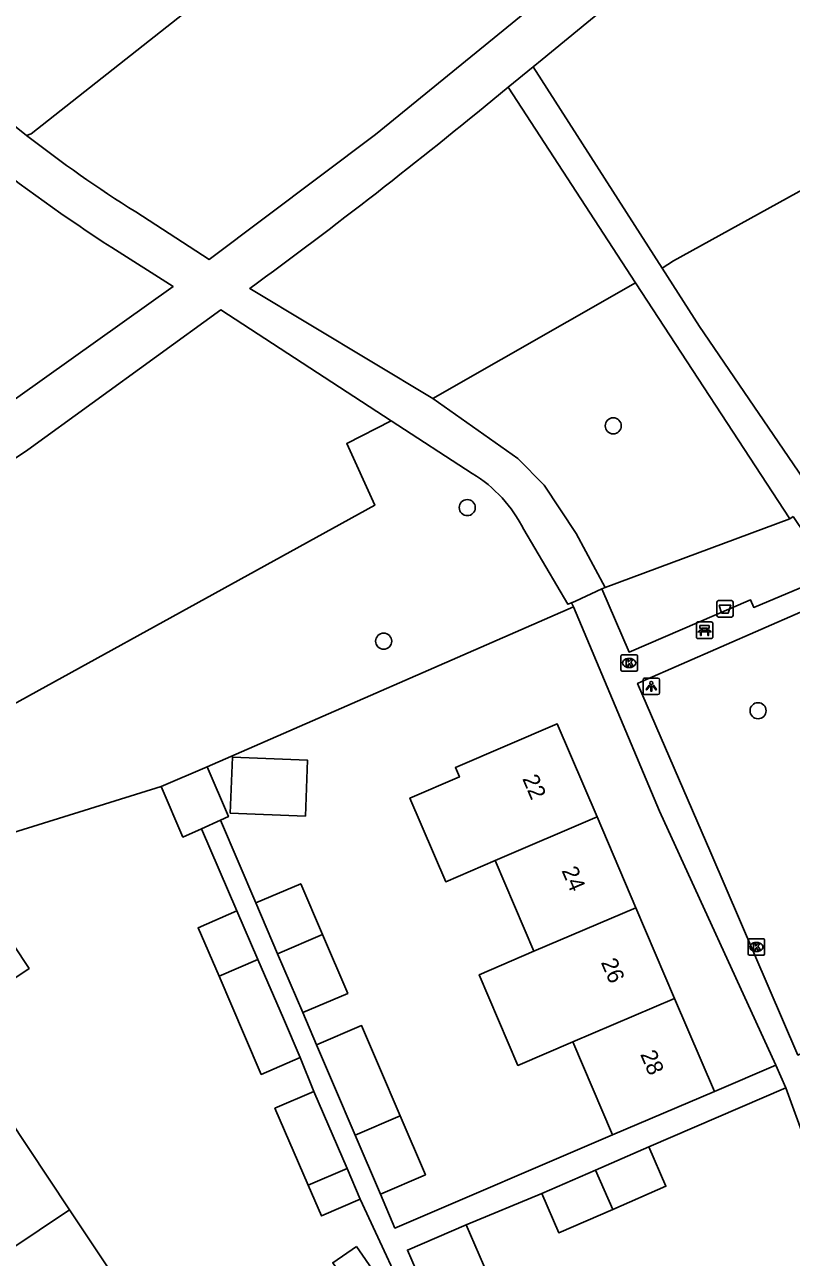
# Model space of a CAD drawing. Extents: x 159353 to 160616, y 385893 to 387321.
# Drawn here: x 159577.9 to 159624.6, y 386440.7 to 386515.7 of the extents above; entities that cross this region are included whole.
import ezdxf

# ---------------------------------------------------------------- set-up
doc = ezdxf.new("R2010")
doc.units = 0
for name, color, linetype in [('IMGEO_Afvalbak', 7, 'Continuous'), ('IMGEO_Bank', 7, 'Continuous'), ('IMGEO_Boom', 7, 'Continuous'), ('IMGEO_Groenvoorziening', 7, 'Continuous'), ('IMGEO_Kolk', 7, 'Continuous'), ('IMGEO_Lichtpunt', 7, 'Continuous'), ('IMGEO_Loofbos', 7, 'Continuous'), ('IMGEO_Pand', 7, 'Continuous'), ('IMGEO_Pand_nummerreeks', 7, 'Continuous'), ('IMGEO_Voetpad_halfverhard', 7, 'Continuous'), ('IMGEO_Voetpad_open', 7, 'Continuous')]:
    doc.layers.add(name, color=color, linetype=linetype)

msp = doc.modelspace()

# ---------------------------------------------------------------- linework, layer by layer
at = {"layer": 'IMGEO_Afvalbak'}
for p, q in [((159620.026, 386479.748), (159620.026, 386480.548)), ((159620.026, 386480.548), (159620.026, 386479.748)), ((159620.126, 386480.648), (159620.916, 386480.648)), ((159620.916, 386480.648), (159620.126, 386480.648)), ((159621.016, 386480.548), (159621.016, 386479.748)), ((159621.016, 386479.748), (159621.016, 386480.548)), ((159620.916, 386479.648), (159620.126, 386479.648)), ((159620.126, 386479.648), (159620.916, 386479.648))]:
    msp.add_line(p, q, dxfattribs=at)
msp.add_lwpolyline([(159620.169, 386480.362), (159620.873, 386480.362), (159620.724, 386479.892), (159620.318, 386479.892), (159620.169, 386480.362)], dxfattribs=at)
for centre, start, end in [((159620.126, 386480.548), 90, 180), ((159620.126, 386480.548), 90, 180), ((159620.916, 386480.548), 0, 90), ((159620.916, 386480.548), 360, 90), ((159620.126, 386479.748), 180, 270), ((159620.126, 386479.748), 180, 270), ((159620.916, 386479.748), 270, 0), ((159620.916, 386479.748), 270, 0)]:
    msp.add_arc(centre, 0.1, start, end, dxfattribs=at)
at = {"layer": 'IMGEO_Bank'}
for p, q in [((159618.777, 386478.421), (159618.777, 386479.262)), ((159618.777, 386479.262), (159618.777, 386478.421)), ((159618.852, 386479.346), (159619.693, 386479.346)), ((159619.693, 386479.346), (159618.852, 386479.346)), ((159619.086, 386478.852), (159619.086, 386478.958)), ((159619.13, 386478.958), (159619.13, 386478.852)), ((159619.418, 386478.964), (159619.136, 386478.964)), ((159619.136, 386478.846), (159619.418, 386478.846)), ((159619.424, 386478.852), (159619.424, 386478.958)), ((159619.468, 386478.958), (159619.468, 386478.852)), ((159619.777, 386479.271), (159619.777, 386478.43)), ((159619.777, 386478.43), (159619.777, 386479.271)), ((159619.702, 386478.346), (159618.861, 386478.346)), ((159618.861, 386478.346), (159619.702, 386478.346)), ((159619.474, 386478.744), (159619.081, 386478.744))]:
    msp.add_line(p, q, dxfattribs=at)
for points in [[(159619.024, 386478.744), (159618.882, 386478.744), (159618.994, 386478.846), (159619.08, 386478.846)], [(159619.08, 386478.964), (159618.994, 386478.964), (159618.994, 386479.125), (159619.557, 386479.125), (159619.557, 386478.964), (159619.474, 386478.964)], [(159619.474, 386478.846), (159619.557, 386478.846), (159619.669, 386478.744), (159619.53, 386478.744)], [(159619.074, 386478.737), (159619.074, 386478.53), (159619.031, 386478.53), (159619.031, 386478.737)], [(159619.524, 386478.737), (159619.524, 386478.53), (159619.48, 386478.53), (159619.48, 386478.737)]]:
    msp.add_lwpolyline(points, dxfattribs=at)
for centre, radius, start, end in [((159618.855, 386479.268), 0.0779, 92.4484, 184.28452), ((159618.855, 386479.268), 0.0779, 92.4484, 184.28452), ((159619.079, 386478.957), 0.00671, 2.89567, 87.10433), ((159619.079, 386478.853), 0.00671, 272.89567, 357.10433), ((159619.136, 386478.957), 0.00671, 92.89567, 177.10433), ((159619.136, 386478.853), 0.00671, 182.89567, 267.10433), ((159619.418, 386478.957), 0.00671, 2.89567, 87.10433), ((159619.418, 386478.853), 0.00671, 272.89567, 357.10433), ((159619.475, 386478.957), 0.00671, 92.89567, 177.10433), ((159619.475, 386478.853), 0.00671, 182.89567, 267.10433), ((159619.699, 386479.268), 0.0779, 2.4484, 94.28452), ((159619.699, 386479.268), 0.0779, 2.4484, 94.28452), ((159618.855, 386478.424), 0.0779, 182.4484, 274.28452), ((159618.855, 386478.424), 0.0779, 182.4484, 274.28452), ((159619.024, 386478.737), 0.00671, 2.89567, 87.10433), ((159619.081, 386478.737), 0.00671, 92.89567, 177.10433), ((159619.473, 386478.737), 0.00671, 2.89567, 87.10433), ((159619.53, 386478.737), 0.00671, 92.89567, 177.10433), ((159619.699, 386478.424), 0.0779, 272.4484, 4.28452), ((159619.699, 386478.424), 0.0779, 272.4484, 4.28452)]:
    msp.add_arc(centre, radius, start, end, dxfattribs=at)
at = {"layer": 'IMGEO_Boom'}
for centre in [(159613.716, 386491.293), (159604.823, 386486.312), (159599.729, 386478.177), (159622.534, 386473.944)]:
    msp.add_circle(centre, 0.489, dxfattribs=at)
at = {"layer": 'IMGEO_Groenvoorziening'}
for points in [[(159667.147, 386524.973), (159656.794, 386519.346), (159660.037, 386510.81), (159635.305, 386500), (159633.396, 386499.166), (159632.966, 386500), (159628.972, 386507.732), (159617.387, 386501.341), (159616.698, 386500.899)], [(159615.073, 386500), (159602.715, 386492.962)], [(159600.187, 386491.603), (159597.482, 386490.226), (159599.199, 386486.465), (159568.818, 386469.742), (159563.351, 386479.984)], [(159624.463, 386485.638), (159613.22, 386481.445)], [(159611.284, 386480.27), (159588.978, 386470.532)], [(159569.941, 386464.28), (159586.179, 386469.337)]]:
    msp.add_lwpolyline(points, dxfattribs=at)
at = {"layer": 'IMGEO_Kolk'}
for p, q in [((159614.26, 386477.351), (159615.112, 386477.351)), ((159614.185, 386476.425), (159614.185, 386477.277)), ((159614.696, 386476.571), (159614.671, 386476.571)), ((159614.673, 386477.131), (159614.698, 386477.131)), ((159615.186, 386477.277), (159615.186, 386476.425)), ((159615.112, 386476.351), (159614.26, 386476.351)), ((159622.009, 386460.055), (159622.861, 386460.055)), ((159621.934, 386459.129), (159621.934, 386459.981)), ((159622.422, 386459.835), (159622.447, 386459.835)), ((159622.935, 386459.981), (159622.935, 386459.129)), ((159622.861, 386459.055), (159622.009, 386459.055)), ((159622.445, 386459.275), (159622.42, 386459.275))]:
    msp.add_line(p, q, dxfattribs=at)
for points in [[(159614.26, 386477.351), (159615.112, 386477.351)], [(159614.185, 386476.425), (159614.185, 386477.277)], [(159614.506, 386477.051), (159614.629, 386477.051), (159614.629, 386476.9), (159614.759, 386477.051), (159614.923, 386477.051), (159614.777, 386476.9), (159614.93, 386476.651), (159614.778, 386476.651), (159614.693, 386476.815), (159614.629, 386476.748), (159614.629, 386476.651), (159614.506, 386476.651), (159614.506, 386477.051)], [(159615.186, 386477.277), (159615.186, 386476.425)], [(159615.112, 386476.351), (159614.26, 386476.351)], [(159622.009, 386460.055), (159622.861, 386460.055)], [(159621.934, 386459.129), (159621.934, 386459.981)], [(159622.255, 386459.755), (159622.378, 386459.755), (159622.378, 386459.604), (159622.508, 386459.755), (159622.672, 386459.755), (159622.526, 386459.604), (159622.679, 386459.355), (159622.527, 386459.355), (159622.442, 386459.519), (159622.378, 386459.452), (159622.378, 386459.355), (159622.255, 386459.355), (159622.255, 386459.755)], [(159622.935, 386459.981), (159622.935, 386459.129)], [(159622.861, 386459.055), (159622.009, 386459.055)]]:
    msp.add_lwpolyline(points, dxfattribs=at)
for centre, start, end in [((159614.262, 386477.275), 91.55205, 178.44795), ((159614.262, 386477.275), 91.55205, 178.44795), ((159615.11, 386477.275), 1.55205, 88.44795), ((159615.11, 386477.275), 1.55205, 88.44795), ((159614.262, 386476.427), 181.55205, 268.44795), ((159614.262, 386476.427), 181.55205, 268.44795), ((159615.11, 386476.427), 271.55205, 358.44795), ((159615.11, 386476.427), 271.55205, 358.44795), ((159622.011, 386459.979), 91.55205, 178.44795), ((159622.011, 386459.979), 91.55205, 178.44795), ((159622.859, 386459.979), 1.55205, 88.44795), ((159622.859, 386459.979), 1.55205, 88.44795), ((159622.011, 386459.131), 181.55205, 268.44795), ((159622.011, 386459.131), 181.55205, 268.44795), ((159622.859, 386459.131), 271.55205, 358.44795), ((159622.859, 386459.131), 271.55205, 358.44795)]:
    msp.add_arc(centre, 0.0765, start, end, dxfattribs=at)
for centre, major_axis, ratio, start_param, end_param in [((159614.672, 386476.851), (-0.387, 0.002), 0.722429, 4.712389, 7.853982), ((159614.697, 386476.851), (-0.39, 0.002), 0.717154, 1.570796, 4.712389), ((159622.421, 386459.555), (-0.387, 0.002), 0.722429, 4.712389, 7.853982), ((159622.446, 386459.555), (-0.39, 0.002), 0.717154, 1.570796, 4.712389)]:
    msp.add_ellipse(centre, major_axis=major_axis, ratio=ratio, start_param=start_param, end_param=end_param, dxfattribs=at)
at = {"layer": 'IMGEO_Lichtpunt'}
for p, q in [((159615.534, 386475.832), (159615.534, 386475.025)), ((159615.534, 386475.832), (159615.534, 386475.025)), ((159616.436, 386475.927), (159615.628, 386475.927)), ((159616.436, 386475.927), (159615.628, 386475.927)), ((159616.53, 386475.025), (159616.53, 386475.832)), ((159616.53, 386475.025), (159616.53, 386475.832)), ((159615.628, 386474.931), (159616.436, 386474.931)), ((159615.628, 386474.931), (159616.436, 386474.931))]:
    msp.add_line(p, q, dxfattribs=at)
for points in [[(159615.908, 386475.496), (159615.947, 386475.468), (159615.759, 386475.206), (159615.721, 386475.233), (159615.908, 386475.496)], [(159616.01, 386475.448), (159616.057, 386475.448), (159616.057, 386475.126), (159616.01, 386475.126), (159616.01, 386475.448)], [(159616.12, 386475.468), (159616.158, 386475.495), (159616.345, 386475.233), (159616.306, 386475.205), (159616.12, 386475.468)]]:
    msp.add_lwpolyline(points, dxfattribs=at)
msp.add_circle((159616.033, 386475.63), 0.0994, dxfattribs=at)
for centre, start, end in [((159615.628, 386475.832), 90, 180), ((159615.628, 386475.832), 90, 180), ((159616.436, 386475.832), 0, 90), ((159616.436, 386475.832), 0, 90), ((159615.628, 386475.025), 180, 270), ((159615.628, 386475.025), 180, 270), ((159616.436, 386475.025), 270, 0), ((159616.436, 386475.025), 270, 360)]:
    msp.add_arc(centre, 0.0946, start, end, dxfattribs=at)
at = {"layer": 'IMGEO_Loofbos'}
msp.add_lwpolyline([(159577.978, 386508.983), (159578.254, 386509.068), (159625.523, 386546.373), (159634.736, 386539.418)], dxfattribs=at)
at = {"layer": 'IMGEO_Pand'}
for points in [[(159606.521, 386464.816), (159603.51, 386463.528), (159601.33, 386468.622), (159604.341, 386469.91), (159604.098, 386470.479), (159610.303, 386473.134), (159612.726, 386467.471)], [(159594.961, 386467.526), (159590.383, 386467.711), (159590.521, 386471.11), (159595.098, 386470.925), (159594.961, 386467.526)], [(159586.179, 386469.337), (159588.978, 386470.532)], [(159588.978, 386470.532), (159590.274, 386467.495), (159589.785, 386467.275)], [(159586.179, 386469.337), (159587.499, 386466.245), (159588.633, 386466.756)], [(159588.633, 386466.756), (159589.785, 386467.275)], [(159606.521, 386464.816), (159612.726, 386467.471)], [(159612.726, 386467.471), (159615.089, 386461.947)], [(159608.884, 386459.292), (159606.521, 386464.816)], [(159569.941, 386464.28), (159570.845, 386462.922), (159573.364, 386459.14), (159576.255, 386461.065), (159578.131, 386458.248), (159575.423, 386456.445), (159575.3, 386456.363), (159573.058, 386454.87)], [(159591.941, 386462.236), (159594.683, 386463.409), (159596.006, 386460.317)], [(159589.7, 386457.77), (159588.423, 386460.729), (159590.792, 386461.751)], [(159590.792, 386461.751), (159592.067, 386458.796)], [(159593.264, 386459.144), (159591.941, 386462.236)], [(159615.089, 386461.947), (159608.884, 386459.292)], [(159615.089, 386461.947), (159617.453, 386456.422)], [(159593.264, 386459.144), (159596.006, 386460.317)], [(159596.006, 386460.317), (159597.542, 386456.728), (159594.8, 386455.555)], [(159611.248, 386453.767), (159607.911, 386452.339), (159605.547, 386457.864), (159608.884, 386459.292)], [(159592.067, 386458.796), (159589.7, 386457.77)], [(159594.646, 386452.815), (159593.62, 386455.195), (159592.067, 386458.796)], [(159594.8, 386455.555), (159593.264, 386459.144)], [(159594.646, 386452.815), (159592.277, 386451.793), (159591.251, 386454.173), (159589.7, 386457.77)], [(159611.248, 386453.767), (159617.453, 386456.422)], [(159617.453, 386456.422), (159619.876, 386450.759)], [(159595.639, 386453.592), (159598.381, 386454.764), (159599.41, 386452.36), (159600.733, 386449.268)], [(159595.639, 386453.592), (159596.668, 386451.187), (159597.991, 386448.095)], [(159613.671, 386448.104), (159611.248, 386453.767)], [(159595.132, 386445.042), (159593.108, 386449.736), (159595.477, 386450.758)], [(159595.477, 386450.758), (159597.499, 386446.069)], [(159619.876, 386450.759), (159613.671, 386448.104)], [(159576.827, 386449.208), (159580.595, 386443.546)], [(159597.991, 386448.095), (159600.733, 386449.268)], [(159600.733, 386449.268), (159602.269, 386445.679), (159599.527, 386444.506)], [(159599.527, 386444.506), (159597.991, 386448.095)], [(159612.638, 386445.966), (159615.889, 386447.375)], [(159615.889, 386447.375), (159616.927, 386444.981), (159613.679, 386443.573)], [(159597.499, 386446.069), (159595.132, 386445.042)], [(159597.499, 386446.069), (159598.305, 386444.202)], [(159609.356, 386444.543), (159612.638, 386445.966)], [(159613.679, 386443.573), (159612.638, 386445.966)], [(159598.305, 386444.202), (159595.936, 386443.18), (159595.132, 386445.042)], [(159613.679, 386443.573), (159610.394, 386442.149), (159609.356, 386444.543)], [(159580.595, 386443.546), (159574.962, 386439.798)], [(159580.595, 386443.546), (159584.363, 386437.885)], [(159602.494, 386438.046), (159601.181, 386441.094), (159604.755, 386442.633)], [(159604.755, 386442.633), (159606.068, 386439.586), (159602.494, 386438.046)], [(159598.077, 386441.321), (159599.218, 386439.672), (159597.773, 386438.672), (159596.631, 386440.32), (159598.077, 386441.321)]]:
    msp.add_lwpolyline(points, dxfattribs=at)
at = {"layer": 'IMGEO_Voetpad_halfverhard'}
for points in [[(159608.831, 386513.153), (159609.376, 386513.596), (159618.553, 386521.16), (159628.208, 386529.625), (159637.343, 386537.912), (159649.609, 386549.736)], [(159634.736, 386539.418), (159621.215, 386527.155), (159617.205, 386523.694), (159599.231, 386509.03), (159589.105, 386501.423), (159584.623, 386504.325)], [(159571.496, 386514.211), (159576.62, 386510.069), (159577.978, 386508.983)], [(159608.831, 386513.153), (159607.306, 386511.913)], [(159616.698, 386500.899), (159608.831, 386513.153)], [(159615.073, 386500), (159607.306, 386511.913)], [(159583.177, 386502.15), (159586.902, 386499.781), (159572.831, 386489.777), (159562.202, 386482.68), (159554.059, 386477.493)], [(159616.698, 386500.899), (159618.977, 386497.348), (159626.206, 386486.751)], [(159592.047, 386500), (159591.571, 386499.651), (159602.715, 386492.962)], [(159624.463, 386485.638), (159615.073, 386500)], [(159563.351, 386479.984), (159578.056, 386489.827), (159589.808, 386498.351), (159600.187, 386491.603)], [(159602.715, 386492.962), (159607.893, 386489.301), (159609.499, 386487.683), (159611.459, 386484.74), (159613.22, 386481.445)], [(159605.128, 386488.391), (159600.187, 386491.603)], [(159624.664, 386485.777), (159624.463, 386485.638)], [(159611.179, 386480.521), (159610.943, 386480.427), (159608.263, 386484.977)], [(159613.22, 386481.445), (159613.016, 386481.357)]]:
    msp.add_lwpolyline(points, dxfattribs=at)
for centre, radius, start, end in [((159396.328, 386766.419), 330.583, 306.30202, 309.65769), ((159626.206, 386570.716), 78.338, 232.00145, 237.93932), ((159633.766, 386581.172), 93.828, 231.27527, 237.37311), ((159600.813, 386481.282), 8.316, 26.37924, 58.74189)]:
    msp.add_arc(centre, radius, start, end, dxfattribs=at)
at = {"layer": 'IMGEO_Voetpad_open'}
for points in [[(159613.016, 386481.357), (159614.676, 386477.518), (159622.066, 386480.699), (159622.275, 386480.229), (159627.041, 386482.24), (159624.664, 386485.777)], [(159613.016, 386481.357), (159611.414, 386480.615), (159611.179, 386480.521)], [(159611.179, 386480.521), (159611.284, 386480.27)], [(159625.229, 386453.082), (159624.96, 386452.966), (159619.656, 386465.294), (159615.201, 386475.602), (159615.457, 386475.714), (159627.534, 386481.006), (159641.381, 386460.032), (159625.229, 386453.082)], [(159611.284, 386480.27), (159616.53, 386467.818), (159623.619, 386452.36)], [(159589.785, 386467.275), (159591.941, 386462.236)], [(159590.792, 386461.751), (159588.633, 386466.756)], [(159594.8, 386455.555), (159595.639, 386453.592)], [(159595.477, 386450.758), (159594.646, 386452.815)], [(159619.876, 386450.759), (159623.619, 386452.36)], [(159623.619, 386452.36), (159624.218, 386450.973)], [(159615.889, 386447.375), (159624.218, 386450.973)], [(159624.218, 386450.973), (159626.632, 386444.407), (159631.354, 386433.532), (159631.603, 386433.04), (159631.733, 386432.748), (159631.965, 386431.993)], [(159599.527, 386444.506), (159600.415, 386442.432), (159613.671, 386448.104)], [(159604.755, 386442.633), (159609.356, 386444.543)], [(159601.776, 386436.734), (159598.305, 386444.202)]]:
    msp.add_lwpolyline(points, dxfattribs=at)

# ---------------------------------------------------------------- texts
at = {"layer": 'IMGEO_Pand_nummerreeks'}
for s, rotation, p in [('22', 293.16447, (159608.158, 386469.808)), ('24', 293.16335, (159610.552, 386464.213)), ('26', 293.16447, (159612.946, 386458.618)), ('28', 293.16335, (159615.34, 386453.023))]:
    msp.add_text(s, height=1, rotation=rotation, dxfattribs=at).set_placement(p)

doc.saveas('drawing.dxf')
